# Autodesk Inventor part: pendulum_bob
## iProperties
Created: 2008-12
Part Number: pendulum_bob
Document SubType Name: Modeling
Designer: Lochan
Density: 1 g/cm^3
Mass: 22.5171 g
Surface Area: 60.7549 cm^2
Volume: 22.5171 cm^3
Author: Lochan
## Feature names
1. Revolution1
2. Extrusion1
3. Extrusion2
4. Mirror1
